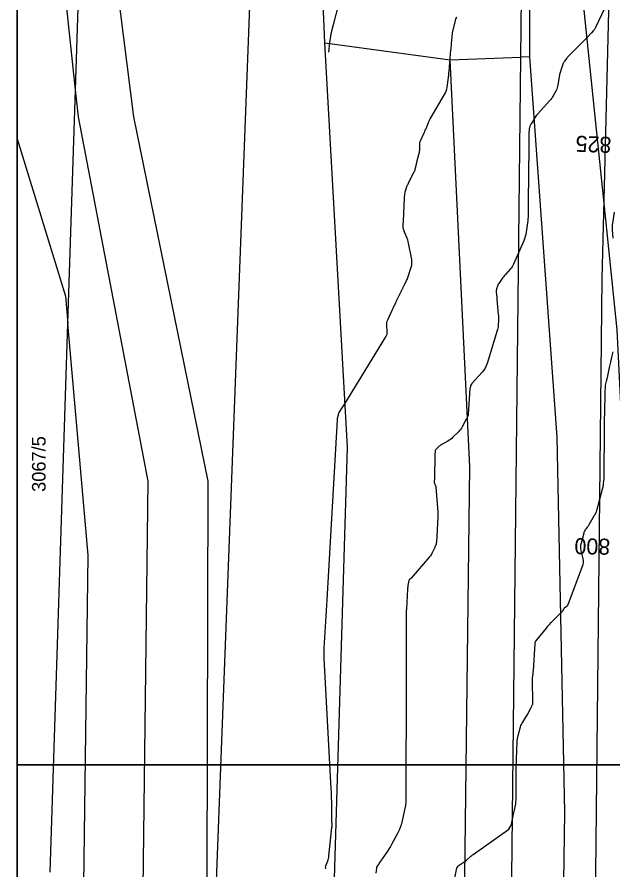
# Model space of a CAD drawing. Extents: x -534410 to -534262, y -1190162 to -1189584.
# Drawn here: x -534410.1 to -534372.9, y -1189801 to -1189747.8 of the extents above; entities that cross this region are included whole.
import ezdxf

# ---------------------------------------------------------------- set-up
doc = ezdxf.new("R2010")
doc.units = 0
for name, color, linetype in [('30', 7, 'Continuous'), ('31', 7, 'Continuous'), ('_N_text', 7, 'Continuous'), ('_rámeček', 7, 'Continuous'), ('_rámeček_mřížka', 7, 'Continuous'), ('Hranice parcel', 7, 'Continuous'), ('Parcelní čísla', 7, 'Continuous')]:
    doc.layers.add(name, color=color, linetype=linetype)

msp = doc.modelspace()

# ---------------------------------------------------------------- linework, layer by layer
at = {"layer": '30'}
for points in [[(-534389.675, -1189745.496), (-534390.401, -1189748.249), (-534390.532, -1189748.817), (-534390.627, -1189749.39), (-534390.685, -1189749.968)], [(-534373.458, -1189747.24), (-534374.015, -1189748.431), (-534374.04, -1189748.478), (-534374.067, -1189748.523), (-534374.097, -1189748.566), (-534374.131, -1189748.607), (-534374.272, -1189748.765), (-534374.307, -1189748.805), (-534374.343, -1189748.843), (-534374.38, -1189748.882), (-534374.417, -1189748.92), (-534375.669, -1189750.182), (-534375.706, -1189750.219), (-534375.741, -1189750.258), (-534375.775, -1189750.298), (-534375.807, -1189750.339), (-534375.958, -1189750.534), (-534375.978, -1189750.562), (-534375.995, -1189750.591), (-534376.01, -1189750.621), (-534376.023, -1189750.652), (-534376.068, -1189750.78), (-534376.08, -1189750.812), (-534376.091, -1189750.845), (-534376.102, -1189750.877), (-534376.112, -1189750.909), (-534376.216, -1189751.231), (-534376.236, -1189751.295), (-534376.253, -1189751.36), (-534376.267, -1189751.426), (-534376.278, -1189751.493), (-534376.359, -1189752.02), (-534376.376, -1189752.11), (-534376.401, -1189752.196), (-534376.434, -1189752.28), (-534376.474, -1189752.362), (-534376.648, -1189752.684), (-534376.694, -1189752.763), (-534376.744, -1189752.838), (-534376.799, -1189752.911), (-534376.858, -1189752.98), (-534377.636, -1189753.843), (-534377.688, -1189753.904), (-534377.738, -1189753.966), (-534377.784, -1189754.031), (-534377.828, -1189754.098), (-534378.037, -1189754.431), (-534378.058, -1189754.468), (-534378.076, -1189754.507), (-534378.091, -1189754.548), (-534378.103, -1189754.59), (-534378.144, -1189754.76), (-534378.153, -1189754.802), (-534378.159, -1189754.845), (-534378.164, -1189754.888), (-534378.166, -1189754.932), (-534378.172, -1189755.169), (-534378.174, -1189755.223), (-534378.175, -1189755.277), (-534378.175, -1189755.331), (-534378.175, -1189755.385), (-534378.175, -1189756.304), (-534378.175, -1189756.358), (-534378.176, -1189756.412), (-534378.177, -1189756.466), (-534378.178, -1189756.52), (-534378.184, -1189756.736), (-534378.186, -1189756.79), (-534378.187, -1189756.844), (-534378.189, -1189756.899), (-534378.191, -1189756.953), (-534378.198, -1189757.188), (-534378.2, -1189757.246), (-534378.201, -1189757.303), (-534378.201, -1189757.36), (-534378.202, -1189757.418), (-534378.202, -1189758.271), (-534378.202, -1189758.329), (-534378.203, -1189758.386), (-534378.204, -1189758.443), (-534378.206, -1189758.501), (-534378.213, -1189758.73), (-534378.215, -1189758.787), (-534378.216, -1189758.845), (-534378.217, -1189758.902), (-534378.217, -1189758.959), (-534378.217, -1189760.107), (-534378.22, -1189760.239), (-534378.227, -1189760.37), (-534378.239, -1189760.5), (-534378.256, -1189760.63), (-534378.342, -1189761.207), (-534378.368, -1189761.345), (-534378.402, -1189761.48), (-534378.445, -1189761.613), (-534378.497, -1189761.744), (-534379.132, -1189763.195), (-534379.175, -1189763.284), (-534379.224, -1189763.368), (-534379.281, -1189763.448), (-534379.344, -1189763.523), (-534379.637, -1189763.846), (-534379.689, -1189763.905), (-534379.739, -1189763.966), (-534379.788, -1189764.028), (-534379.834, -1189764.092), (-534380.052, -1189764.403), (-534380.078, -1189764.442), (-534380.1, -1189764.484), (-534380.119, -1189764.527), (-534380.135, -1189764.572), (-534380.19, -1189764.754), (-534380.201, -1189764.799), (-534380.208, -1189764.845), (-534380.211, -1189764.892), (-534380.209, -1189764.939), (-534380.179, -1189765.28), (-534380.169, -1189765.389), (-534380.083, -1189766.351), (-534380.077, -1189766.435), (-534380.073, -1189766.52), (-534380.073, -1189766.604), (-534380.074, -1189766.688), (-534380.087, -1189767.026), (-534380.093, -1189767.11), (-534380.104, -1189767.193), (-534380.121, -1189767.275), (-534380.143, -1189767.357), (-534380.773, -1189769.408), (-534380.829, -1189769.559), (-534380.899, -1189769.701), (-534380.986, -1189769.835), (-534381.087, -1189769.959), (-534381.723, -1189770.659), (-534381.733, -1189770.67), (-534381.742, -1189770.682), (-534381.751, -1189770.694), (-534381.759, -1189770.706), (-534381.797, -1189770.768), (-534381.801, -1189770.775), (-534381.805, -1189770.782), (-534381.808, -1189770.789), (-534381.81, -1189770.797), (-534381.819, -1189770.837), (-534381.825, -1189770.86), (-534381.841, -1189770.923), (-534381.845, -1189770.937), (-534381.847, -1189770.95), (-534381.849, -1189770.963), (-534381.85, -1189770.977), (-534381.954, -1189772.572), (-534381.957, -1189772.6), (-534381.963, -1189772.629), (-534381.971, -1189772.656), (-534381.981, -1189772.684), (-534382.028, -1189772.791), (-534382.04, -1189772.818), (-534382.052, -1189772.844), (-534382.065, -1189772.87), (-534382.079, -1189772.896), (-534382.335, -1189773.359), (-534382.385, -1189773.443), (-534382.44, -1189773.522), (-534382.501, -1189773.598), (-534382.568, -1189773.669), (-534382.918, -1189774.02), (-534382.99, -1189774.086), (-534383.065, -1189774.147), (-534383.145, -1189774.203), (-534383.228, -1189774.253), (-534383.651, -1189774.486), (-534383.696, -1189774.513), (-534383.738, -1189774.543), (-534383.777, -1189774.577), (-534383.814, -1189774.613), (-534383.975, -1189774.789), (-534383.998, -1189774.818), (-534384.015, -1189774.849), (-534384.026, -1189774.883), (-534384.031, -1189774.92), (-534384.04, -1189775.071), (-534384.042, -1189775.108), (-534384.044, -1189775.146), (-534384.045, -1189775.184), (-534384.046, -1189775.222), (-534384.063, -1189776.443), (-534384.064, -1189776.483), (-534384.065, -1189776.523), (-534384.067, -1189776.563), (-534384.07, -1189776.604), (-534384.082, -1189776.78), (-534384.082, -1189776.812), (-534384.078, -1189776.843), (-534384.07, -1189776.873), (-534384.059, -1189776.903), (-534384.005, -1189777.02), (-534383.992, -1189777.05), (-534383.983, -1189777.08), (-534383.976, -1189777.111), (-534383.972, -1189777.143), (-534383.854, -1189778.685), (-534383.853, -1189778.711), (-534383.851, -1189778.737), (-534383.85, -1189778.763), (-534383.849, -1189778.789), (-534383.846, -1189778.894), (-534383.846, -1189778.92), (-534383.846, -1189778.946), (-534383.847, -1189778.973), (-534383.848, -1189778.999), (-534383.948, -1189780.581), (-534383.951, -1189780.608), (-534383.955, -1189780.635), (-534383.962, -1189780.662), (-534383.97, -1189780.688), (-534384.008, -1189780.792), (-534384.017, -1189780.818), (-534384.027, -1189780.844), (-534384.038, -1189780.869), (-534384.05, -1189780.895), (-534384.211, -1189781.242), (-534384.244, -1189781.307), (-534384.281, -1189781.369), (-534384.323, -1189781.428), (-534384.368, -1189781.485), (-534385.516, -1189782.817), (-534385.528, -1189782.83), (-534385.541, -1189782.843), (-534385.555, -1189782.855), (-534385.569, -1189782.866), (-534385.628, -1189782.908), (-534385.642, -1189782.92), (-534385.652, -1189782.933), (-534385.66, -1189782.949), (-534385.664, -1189782.966), (-534385.722, -1189783.273), (-534385.731, -1189783.33), (-534385.739, -1189783.387), (-534385.745, -1189783.445), (-534385.749, -1189783.503), (-534385.815, -1189784.752), (-534385.816, -1189784.762), (-534385.817, -1189784.771), (-534385.819, -1189784.78), (-534385.822, -1189784.79), (-534385.832, -1189784.826), (-534385.834, -1189784.835), (-534385.836, -1189784.845), (-534385.837, -1189784.854), (-534385.837, -1189784.864), (-534385.837, -1189790.82), (-534385.837, -1189790.844), (-534385.838, -1189790.869), (-534385.839, -1189790.917), (-534385.84, -1189790.941), (-534385.84, -1189790.965), (-534385.84, -1189792.724), (-534385.84, -1189792.748), (-534385.84, -1189792.772), (-534385.842, -1189792.832), (-534385.843, -1189792.869), (-534385.845, -1189792.921), (-534385.845, -1189792.934), (-534385.845, -1189792.947), (-534385.846, -1189792.96), (-534385.846, -1189792.973), (-534385.846, -1189794.716), (-534385.846, -1189794.729), (-534385.846, -1189794.742), (-534385.846, -1189794.755), (-534385.846, -1189794.768), (-534385.848, -1189794.819), (-534385.849, -1189794.832), (-534385.849, -1189794.845), (-534385.849, -1189794.857), (-534385.849, -1189794.87), (-534385.849, -1189796.811), (-534385.85, -1189796.828), (-534385.851, -1189796.844), (-534385.853, -1189796.861), (-534385.856, -1189796.878), (-534385.869, -1189796.944), (-534385.876, -1189796.977), (-534385.882, -1189797.01), (-534386.104, -1189798.05), (-534386.148, -1189798.226), (-534386.205, -1189798.398), (-534386.274, -1189798.566), (-534386.355, -1189798.728), (-534386.753, -1189799.461), (-534386.821, -1189799.581), (-534386.891, -1189799.699), (-534386.964, -1189799.815), (-534387.041, -1189799.93), (-534387.468, -1189800.551), (-534387.489, -1189800.581), (-534387.509, -1189800.61), (-534387.529, -1189800.639), (-534387.549, -1189800.669), (-534387.663, -1189800.833), (-534387.667, -1189800.839), (-534387.67, -1189800.845), (-534387.673, -1189800.851), (-534387.676, -1189800.858), (-534387.685, -1189800.885), (-534387.687, -1189800.892), (-534387.688, -1189800.899), (-534387.69, -1189800.906), (-534387.691, -1189800.913), (-534387.73, -1189801.248)]]:
    msp.add_lwpolyline(points, dxfattribs=at)
at = {"layer": '31'}
for points in [[(-534390.843, -1189800.964), (-534390.857, -1189800.933), (-534390.862, -1189800.864), (-534390.845, -1189800.79), (-534390.732, -1189800.482), (-534390.706, -1189800.404), (-534390.685, -1189800.325), (-534390.669, -1189800.245), (-534390.657, -1189800.164), (-534390.465, -1189798.386), (-534390.461, -1189798.337), (-534390.459, -1189798.287), (-534390.459, -1189798.238), (-534390.462, -1189798.188), (-534390.477, -1189797.99), (-534390.48, -1189797.941), (-534390.483, -1189797.891), (-534390.484, -1189797.842), (-534390.484, -1189797.792), (-534390.484, -1189796.747), (-534390.486, -1189796.556), (-534390.49, -1189796.365), (-534390.496, -1189796.175), (-534390.506, -1189795.984), (-534390.938, -1189788.199), (-534390.952, -1189787.863), (-534390.956, -1189787.527), (-534390.949, -1189787.192), (-534390.932, -1189786.857), (-534390.845, -1189785.515), (-534390.823, -1189785.18), (-534390.803, -1189784.844), (-534390.783, -1189784.509), (-534390.763, -1189784.173), (-534390.128, -1189772.923), (-534390.125, -1189772.884), (-534390.12, -1189772.845), (-534390.113, -1189772.806), (-534390.105, -1189772.768), (-534390.068, -1189772.614), (-534390.058, -1189772.577), (-534390.044, -1189772.54), (-534390.028, -1189772.505), (-534390.008, -1189772.471), (-534389.82, -1189772.172), (-534389.782, -1189772.111), (-534389.743, -1189772.049), (-534389.705, -1189771.988), (-534389.668, -1189771.927), (-534387.099, -1189767.745), (-534387.057, -1189767.664), (-534387.029, -1189767.58), (-534387.016, -1189767.492), (-534387.016, -1189767.401), (-534387.046, -1189767.03), (-534387.047, -1189766.938), (-534387.037, -1189766.849), (-534387.016, -1189766.761), (-534386.982, -1189766.676), (-534386.689, -1189766.04), (-534386.667, -1189765.992), (-534386.644, -1189765.943), (-534386.621, -1189765.895), (-534386.598, -1189765.847), (-534386.504, -1189765.655), (-534386.481, -1189765.607), (-534386.457, -1189765.559), (-534386.434, -1189765.51), (-534386.411, -1189765.462), (-534386.146, -1189764.908), (-534386.131, -1189764.876), (-534386.116, -1189764.844), (-534386.101, -1189764.813), (-534386.086, -1189764.781), (-534386.026, -1189764.654), (-534386.011, -1189764.623), (-534385.996, -1189764.591), (-534385.98, -1189764.56), (-534385.965, -1189764.529), (-534385.806, -1189764.22), (-534385.776, -1189764.158), (-534385.748, -1189764.095), (-534385.723, -1189764.03), (-534385.701, -1189763.965), (-534385.515, -1189763.385), (-534385.485, -1189763.266), (-534385.471, -1189763.146), (-534385.472, -1189763.025), (-534385.489, -1189762.904), (-534385.714, -1189761.781), (-534385.73, -1189761.708), (-534385.751, -1189761.636), (-534385.775, -1189761.565), (-534385.802, -1189761.496), (-534385.956, -1189761.137), (-534385.967, -1189761.109), (-534385.977, -1189761.081), (-534385.985, -1189761.052), (-534385.991, -1189761.022), (-534386.012, -1189760.904), (-534386.016, -1189760.874), (-534386.019, -1189760.844), (-534386.02, -1189760.814), (-534386.019, -1189760.784), (-534386.013, -1189760.645), (-534386.009, -1189760.578), (-534386.006, -1189760.512), (-534385.935, -1189759.081), (-534385.931, -1189759.01), (-534385.925, -1189758.883), (-534385.924, -1189758.864), (-534385.922, -1189758.845), (-534385.92, -1189758.825), (-534385.917, -1189758.806), (-534385.903, -1189758.729), (-534385.9, -1189758.71), (-534385.895, -1189758.691), (-534385.89, -1189758.672), (-534385.884, -1189758.654), (-534385.782, -1189758.363), (-534385.761, -1189758.309), (-534385.74, -1189758.255), (-534385.716, -1189758.202), (-534385.691, -1189758.15), (-534385.327, -1189757.422), (-534385.302, -1189757.368), (-534385.28, -1189757.312), (-534385.261, -1189757.255), (-534385.246, -1189757.197), (-534385.192, -1189756.962), (-534385.178, -1189756.903), (-534385.165, -1189756.845), (-534385.151, -1189756.786), (-534385.137, -1189756.727), (-534385.011, -1189756.202), (-534384.999, -1189756.143), (-534384.99, -1189756.084), (-534384.985, -1189756.025), (-534384.984, -1189755.965), (-534384.984, -1189755.724), (-534384.98, -1189755.665), (-534384.971, -1189755.607), (-534384.955, -1189755.55), (-534384.934, -1189755.495), (-534384.708, -1189755.001), (-534384.673, -1189754.923), (-534384.639, -1189754.844), (-534384.606, -1189754.764), (-534384.574, -1189754.684), (-534384.448, -1189754.363), (-534384.415, -1189754.284), (-534384.378, -1189754.206), (-534384.339, -1189754.13), (-534384.296, -1189754.055), (-534383.43, -1189752.617), (-534383.372, -1189752.508), (-534383.326, -1189752.394), (-534383.292, -1189752.277), (-534383.27, -1189752.155), (-534383.194, -1189751.553), (-534383.185, -1189751.482), (-534383.177, -1189751.411), (-534383.17, -1189751.341), (-534383.163, -1189751.27), (-534383.137, -1189750.986), (-534383.131, -1189750.915), (-534383.125, -1189750.844), (-534383.119, -1189750.774), (-534383.113, -1189750.703), (-534383.084, -1189750.323), (-534383.078, -1189750.248), (-534383.071, -1189750.174), (-534383.064, -1189750.099), (-534383.057, -1189750.024), (-534383.026, -1189749.726), (-534383.019, -1189749.651), (-534383.012, -1189749.577), (-534383.006, -1189749.502), (-534383, -1189749.427), (-534382.97, -1189749.028), (-534382.962, -1189748.936), (-534382.949, -1189748.846), (-534382.933, -1189748.755), (-534382.914, -1189748.666), (-534382.73, -1189747.896), (-534382.726, -1189747.88), (-534382.721, -1189747.866), (-534382.714, -1189747.851), (-534382.706, -1189747.838), (-534382.672, -1189747.784), (-534382.664, -1189747.77)], [(-534372.918, -1189761.59), (-534372.955, -1189761.052), (-534372.959, -1189760.948), (-534372.957, -1189760.845), (-534372.948, -1189760.742), (-534372.934, -1189760.639), (-534372.819, -1189759.949)], [(-534382.813, -1189801.684), (-534382.694, -1189801.008), (-534382.673, -1189800.931), (-534382.638, -1189800.862), (-534382.59, -1189800.802), (-534382.528, -1189800.751), (-534382.22, -1189800.54), (-534382.169, -1189800.505), (-534382.12, -1189800.467), (-534382.071, -1189800.428), (-534382.024, -1189800.388), (-534381.837, -1189800.224), (-534381.789, -1189800.184), (-534381.741, -1189800.145), (-534381.692, -1189800.107), (-534381.642, -1189800.07), (-534379.515, -1189798.56), (-534379.426, -1189798.484), (-534379.355, -1189798.396), (-534379.302, -1189798.296), (-534379.267, -1189798.184), (-534379.13, -1189797.554), (-534379.078, -1189797.317), (-534379.01, -1189797.002), (-534378.995, -1189796.923), (-534378.984, -1189796.844), (-534378.977, -1189796.764), (-534378.975, -1189796.683), (-534378.975, -1189795.036), (-534378.975, -1189794.94), (-534378.974, -1189794.845), (-534378.972, -1189794.749), (-534378.969, -1189794.653), (-534378.951, -1189794.146), (-534378.95, -1189794.098), (-534378.947, -1189794.05), (-534378.945, -1189794.002), (-534378.942, -1189793.953), (-534378.929, -1189793.761), (-534378.926, -1189793.713), (-534378.924, -1189793.665), (-534378.921, -1189793.617), (-534378.92, -1189793.569), (-534378.903, -1189793.05), (-534378.897, -1189792.948), (-534378.884, -1189792.846), (-534378.866, -1189792.746), (-534378.841, -1189792.647), (-534378.69, -1189792.107), (-534378.664, -1189792.026), (-534378.633, -1189791.949), (-534378.595, -1189791.874), (-534378.552, -1189791.801), (-534378.355, -1189791.499), (-534378.315, -1189791.437), (-534378.277, -1189791.373), (-534378.24, -1189791.308), (-534378.206, -1189791.242), (-534378.025, -1189790.888), (-534378.014, -1189790.866), (-534378.003, -1189790.844), (-534377.993, -1189790.822), (-534377.983, -1189790.8), (-534377.942, -1189790.71), (-534377.934, -1189790.687), (-534377.927, -1189790.664), (-534377.924, -1189790.64), (-534377.923, -1189790.616), (-534377.942, -1189789.134), (-534377.942, -1189789.089), (-534377.94, -1189789.044), (-534377.936, -1189789), (-534377.931, -1189788.956), (-534377.909, -1189788.779), (-534377.903, -1189788.735), (-534377.899, -1189788.69), (-534377.895, -1189788.646), (-534377.891, -1189788.601), (-534377.78, -1189786.89), (-534377.78, -1189786.881), (-534377.779, -1189786.872), (-534377.78, -1189786.852), (-534377.779, -1189786.845), (-534377.778, -1189786.837), (-534377.774, -1189786.823), (-534377.771, -1189786.816), (-534377.768, -1189786.81), (-534377.75, -1189786.78), (-534377.747, -1189786.774), (-534377.743, -1189786.768), (-534377.739, -1189786.762), (-534377.734, -1189786.757), (-534377.08, -1189785.932), (-534376.984, -1189785.815), (-534376.885, -1189785.702), (-534376.783, -1189785.591), (-534376.677, -1189785.483), (-534376.071, -1189784.882), (-534376.053, -1189784.863), (-534376.036, -1189784.842), (-534376.022, -1189784.82), (-534376.009, -1189784.796), (-534375.96, -1189784.7), (-534375.947, -1189784.677), (-534375.931, -1189784.656), (-534375.913, -1189784.637), (-534375.892, -1189784.62), (-534375.791, -1189784.549), (-534375.769, -1189784.531), (-534375.75, -1189784.51), (-534375.734, -1189784.486), (-534375.722, -1189784.46), (-534374.823, -1189782.072), (-534374.787, -1189781.953), (-534374.77, -1189781.832), (-534374.77, -1189781.71), (-534374.789, -1189781.587), (-534374.903, -1189781.086), (-534374.923, -1189780.965), (-534374.928, -1189780.845), (-534374.918, -1189780.725), (-534374.893, -1189780.605), (-534374.726, -1189779.988), (-534374.711, -1189779.939), (-534374.691, -1189779.892), (-534374.667, -1189779.848), (-534374.638, -1189779.805), (-534374.516, -1189779.639), (-534374.486, -1189779.597), (-534374.457, -1189779.554), (-534374.429, -1189779.511), (-534374.402, -1189779.467), (-534374.066, -1189778.892), (-534374.052, -1189778.868), (-534374.039, -1189778.844), (-534374.026, -1189778.82), (-534374.014, -1189778.795), (-534373.964, -1189778.697), (-534373.953, -1189778.672), (-534373.943, -1189778.647), (-534373.934, -1189778.621), (-534373.926, -1189778.594), (-534373.557, -1189777.182), (-534373.543, -1189777.122), (-534373.53, -1189777.061), (-534373.52, -1189777), (-534373.511, -1189776.939), (-534373.482, -1189776.692), (-534373.476, -1189776.631), (-534373.472, -1189776.569), (-534373.469, -1189776.507), (-534373.468, -1189776.445), (-534373.468, -1189775.189), (-534373.468, -1189775.154), (-534373.466, -1189775.12), (-534373.465, -1189775.085), (-534373.462, -1189775.051), (-534373.45, -1189774.913), (-534373.447, -1189774.879), (-534373.445, -1189774.844), (-534373.444, -1189774.81), (-534373.444, -1189774.775), (-534373.443, -1189774.619), (-534373.443, -1189774.582), (-534373.443, -1189774.544), (-534373.443, -1189774.507), (-534373.443, -1189774.469), (-534373.443, -1189773.22), (-534373.443, -1189773.145), (-534373.443, -1189773.07), (-534373.442, -1189772.92), (-534373.442, -1189772.882), (-534373.442, -1189772.845), (-534373.441, -1189772.807), (-534373.441, -1189772.769), (-534373.439, -1189772.615), (-534373.438, -1189772.577), (-534373.437, -1189772.539), (-534373.436, -1189772.5), (-534373.435, -1189772.462), (-534373.404, -1189771.271), (-534373.403, -1189771.228), (-534373.402, -1189771.185), (-534373.402, -1189771.143), (-534373.401, -1189771.1), (-534373.398, -1189770.93), (-534373.397, -1189770.887), (-534373.393, -1189770.845), (-534373.387, -1189770.803), (-534373.378, -1189770.761), (-534373.321, -1189770.509), (-534373.309, -1189770.453), (-534373.296, -1189770.397), (-534373.283, -1189770.341), (-534373.271, -1189770.286), (-534373.13, -1189769.657), (-534373.112, -1189769.575), (-534373.093, -1189769.494), (-534373.075, -1189769.413), (-534373.057, -1189769.332), (-534372.983, -1189769.007), (-534372.965, -1189768.926), (-534372.949, -1189768.844), (-534372.933, -1189768.762), (-534372.919, -1189768.68)]]:
    msp.add_lwpolyline(points, dxfattribs=at)
at = {"layer": '_rámeček'}
msp.add_line((-534410.126, -1189584.47), (-534410.126, -1190161.97), dxfattribs=at)
for points in [[(-534410.126, -1189689.47), (-534261.626, -1189689.47), (-534261.626, -1189794.47), (-534410.126, -1189794.47)], [(-534410.126, -1189794.47), (-534261.626, -1189794.47), (-534261.626, -1189899.47), (-534410.126, -1189899.47)]]:
    msp.add_lwpolyline(points, close=True, dxfattribs=at)
at = {"layer": '_rámeček_mřížka'}
for p, q in [((-534410.126, -1189584.47), (-534410.126, -1190161.97)), ((-534407.126, -1189794.47), (-534410.126, -1189794.47))]:
    msp.add_line(p, q, dxfattribs=at)
at = {"layer": 'Hranice parcel'}
for p, q in [((-534371.04, -1189658.4), (-534373.49, -1189759.21)), ((-534378.67, -1189750.28), (-534377.8, -1189671.05)), ((-534406.48, -1189752.31), (-534404.82, -1189701)), ((-534398.3, -1189817.87), (-534394.19, -1189710.57)), ((-534390.92, -1189749.37), (-534383.09, -1189750.44)), ((-534383.09, -1189750.44), (-534378.67, -1189750.28)), ((-534378.12, -1189750.26), (-534378.67, -1189750.28)), ((-534406.95, -1189766.9), (-534406.48, -1189752.31)), ((-534373.49, -1189759.21), (-534373.61, -1189764.09)), ((-534408.06, -1189801.17), (-534406.95, -1189766.9))]:
    msp.add_line(p, q, dxfattribs=at)
for points in [[(-534373.49, -1189759.21), (-534375.27, -1189742.09), (-534373.87, -1189702.99), (-534373.87, -1189662.03), (-534374.42, -1189646.7)], [(-534378.12, -1189750.26), (-534378.12, -1189746.17), (-534376.49, -1189693.82), (-534377.8, -1189671.05)], [(-534406.48, -1189752.31), (-534408.29, -1189735.19), (-534406.08, -1189700.59)], [(-534398.3, -1189817.87), (-534398.2, -1189776.76), (-534402.83, -1189754), (-534404.51, -1189740.82), (-534402.1, -1189701.89)], [(-534390.92, -1189749.37), (-534391.09, -1189744.93), (-534393.26, -1189731.27), (-534393.26, -1189715.05), (-534394.19, -1189710.57)], [(-534395.93, -1189955.06), (-534393.76, -1189916.2), (-534389.49, -1189774.63), (-534390.92, -1189749.37)], [(-534385.61, -1189919.11), (-534380.06, -1189877.29), (-534378.67, -1189750.28)], [(-534383.94, -1189956.8), (-534379.19, -1189918.48), (-534376.74, -1189853.94), (-534375.92, -1189797.44), (-534376.41, -1189774.02), (-534378.12, -1189750.26)], [(-534385.61, -1189919.11), (-534383.81, -1189892.54), (-534382.22, -1189804.86), (-534381.85, -1189775.86), (-534383.09, -1189750.44)], [(-534406.13, -1189942), (-534403.45, -1189886.77), (-534402.68, -1189837.82), (-534401.95, -1189776.76), (-534406.3, -1189754), (-534406.48, -1189752.31)], [(-534410.126, -1189755.374), (-534407.1, -1189765.2), (-534406.95, -1189766.9)], [(-534369.38, -1189820.8), (-534370.35, -1189813.98), (-534372.65, -1189767.31), (-534373.49, -1189759.21)], [(-534373.61, -1189764.09), (-534375.04, -1189897.07), (-534384.28, -1189963.65)], [(-534410.126, -1189932.794), (-534408.16, -1189899.66), (-534406.57, -1189847.9), (-534405.68, -1189781.38), (-534406.95, -1189766.9)]]:
    msp.add_lwpolyline(points, dxfattribs=at)

# ---------------------------------------------------------------- texts
at = {"layer": '_N_text'}
for s, rotation, p in [('825', 177.8451, (-534373.004, -1189755.263)), ('800', 178.6463, (-534373.082, -1189780.36))]:
    msp.add_text(s, height=1, rotation=rotation, dxfattribs=at).set_placement(p)
at = {"layer": 'Parcelní čísla'}
msp.add_text('3067/5', height=0.85, rotation=90, dxfattribs=at).set_placement((-534408.344, -1189777.427))

doc.saveas('drawing.dxf')
